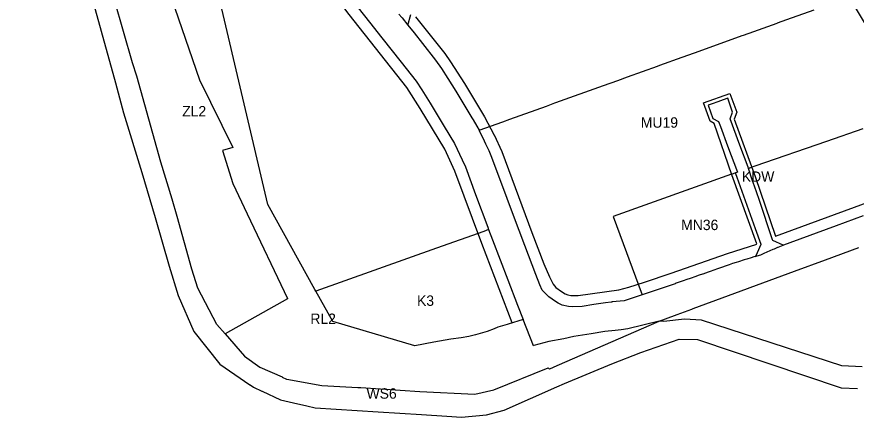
# Model space of a CAD drawing. Extents: x 7428080 to 7432143, y 5545880 to 5549217.
# Drawn here: x 7430737.9 to 7431185, y 5546637.9 to 5546851.1 of the extents above; entities that cross this region are included whole.
import ezdxf

# ---------------------------------------------------------------- set-up
doc = ezdxf.new("R2010")
doc.units = 0
for name, color, linetype in [('CZ_L_linie rozgraniczające tereny o różnym przeznaczeniu oraz różnych warunkach ich zabudowy i zagospodarowania', 7, 'Continuous'), ('CZ_L_maksymalne nieprzekraczalne linie zabudowy', 7, 'Continuous'), ('CZ_L_opisy_linie rozgraniczające tereny o różnym przeznaczeniu oraz różnych warunkach ich zabudowy i zagospodarowania', 7, 'Continuous')]:
    doc.layers.add(name, color=color, linetype=linetype)

msp = doc.modelspace()

# ---------------------------------------------------------------- linework, layer by layer
at = {"layer": 'CZ_L_linie rozgraniczające tereny o różnym przeznaczeniu oraz różnych warunkach ich zabudowy i zagospodarowania'}
for p, q in [((7430772.09, 5546882.16), (7430782.77, 5546843.47)), ((7430816.73, 5546871.65), (7430835.13, 5546817.59)), ((7430871.63, 5546751.13), (7430842.37, 5546875.38)), ((7430799.48, 5546826.52), (7430789.89, 5546859.94)), ((7430919.75, 5546855.93), (7430925.7, 5546848.35)), ((7431148.11, 5546849.64), (7431162.61, 5546854.85)), ((7430941.47, 5546852.61), (7430942.98, 5546850.71)), ((7430942.98, 5546850.71), (7430943.1, 5546850.55)), ((7430943.1, 5546850.55), (7430946.25, 5546846.58)), ((7430946.25, 5546846.58), (7430947.77, 5546852.28)), ((7431143.09, 5546847.84), (7431148.11, 5546849.64)), ((7430925.7, 5546848.35), (7430932.34, 5546839.98)), ((7430946.25, 5546846.58), (7430949.49, 5546842.5)), ((7431130.47, 5546843.3), (7431142.95, 5546847.79)), ((7431142.95, 5546847.79), (7431143.09, 5546847.84)), ((7430782.77, 5546843.47), (7430790.38, 5546816)), ((7430949.49, 5546842.5), (7430953.96, 5546836.87)), ((7431101.34, 5546832.83), (7431124.29, 5546841.08)), ((7431124.29, 5546841.08), (7431124.96, 5546841.32)), ((7431124.96, 5546841.32), (7431130.47, 5546843.3)), ((7430932.34, 5546839.98), (7430942.62, 5546827.04)), ((7430953.96, 5546836.87), (7430960.97, 5546828.08)), ((7431092.28, 5546829.58), (7431098.94, 5546831.97)), ((7431098.94, 5546831.97), (7431101.34, 5546832.83)), ((7430942.62, 5546827.04), (7430950.62, 5546816.8)), ((7430960.97, 5546828.08), (7430964.09, 5546823.59)), ((7431080.47, 5546825.33), (7431092.28, 5546829.58)), ((7430801.85, 5546819.49), (7430799.48, 5546826.52)), ((7430964.09, 5546823.59), (7430967.54, 5546818.25)), ((7431063.25, 5546819.15), (7431079.15, 5546824.86)), ((7431079.15, 5546824.86), (7431080.47, 5546825.33)), ((7430814.59, 5546773.7), (7430801.85, 5546819.49)), ((7430967.54, 5546818.25), (7430971.78, 5546811.47)), ((7431057.96, 5546817.25), (7431063.25, 5546819.15)), ((7430790.38, 5546816), (7430794.65, 5546799.9)), ((7430835.13, 5546817.59), (7430852.91, 5546781.48)), ((7430950.62, 5546816.8), (7430953.57, 5546812.23)), ((7431025, 5546805.4), (7431050.35, 5546814.51)), ((7431050.35, 5546814.51), (7431057.96, 5546817.25)), ((7430953.57, 5546812.23), (7430958.13, 5546805.06)), ((7430971.78, 5546811.47), (7430975.49, 5546805.32)), ((7430958.13, 5546805.06), (7430965.59, 5546792.7)), ((7430975.49, 5546805.32), (7430980.3, 5546797.35)), ((7431019.98, 5546803.6), (7431024.52, 5546805.23)), ((7431024.52, 5546805.23), (7431025, 5546805.4)), ((7431108.36, 5546804.79), (7431106.19, 5546804.01)), ((7431111.3, 5546805.84), (7431108.36, 5546804.79)), ((7431114.17, 5546806.87), (7431111.3, 5546805.84)), ((7431116.64, 5546807.75), (7431114.17, 5546806.87)), ((7431119.21, 5546800.25), (7431116.64, 5546807.75)), ((7431000.48, 5546796.59), (7431019.98, 5546803.6)), ((7431106.19, 5546804.01), (7431108.63, 5546796.89)), ((7431117.91, 5546796.73), (7431119.21, 5546800.25)), ((7430794.65, 5546799.9), (7430804.53, 5546768.24)), ((7430980.3, 5546797.35), (7430980.94, 5546796.3)), ((7430980.94, 5546796.3), (7430982.96, 5546792.95)), ((7430996.75, 5546795.25), (7431000.48, 5546796.59)), ((7431108.63, 5546796.89), (7431111.74, 5546795.33)), ((7431123.08, 5546782.72), (7431117.91, 5546796.73)), ((7430965.59, 5546792.7), (7430971.02, 5546783.71)), ((7430982.96, 5546792.95), (7430984.24, 5546790.75)), ((7430984.24, 5546790.75), (7430996.75, 5546795.25)), ((7431111.74, 5546795.33), (7431112.71, 5546792.62)), ((7431112.71, 5546792.62), (7431116.51, 5546782.44)), ((7431188.57, 5546791.51), (7431169.17, 5546784.73)), ((7430984.42, 5546790.45), (7430984.24, 5546790.75)), ((7430987.03, 5546784.91), (7430984.42, 5546790.45)), ((7430971.02, 5546783.71), (7430975.11, 5546775.01)), ((7430987.8, 5546783.27), (7430987.03, 5546784.91)), ((7430989.46, 5546779.75), (7430987.8, 5546783.27)), ((7431116.51, 5546782.44), (7431121.82, 5546768.34)), ((7431127.39, 5546771.04), (7431123.08, 5546782.72)), ((7431169.17, 5546784.73), (7431131.02, 5546771.55)), ((7430852.91, 5546781.48), (7430847.46, 5546779.98)), ((7430847.46, 5546779.98), (7430852.88, 5546762.35)), ((7430990.6, 5546777.16), (7430989.46, 5546779.75)), ((7430820.58, 5546753.96), (7430814.59, 5546773.7)), ((7430975.11, 5546775.01), (7430976.82, 5546771.2)), ((7430995.73, 5546763.44), (7430990.6, 5546777.16)), ((7430976.82, 5546771.2), (7430982.29, 5546756.46)), ((7431127.62, 5546770.36), (7431127.39, 5546771.04)), ((7431129.85, 5546763.84), (7431127.62, 5546770.36)), ((7431127.64, 5546770.36), (7431127.62, 5546770.36)), ((7431128.09, 5546770.52), (7431127.64, 5546770.36)), ((7431128.1, 5546770.52), (7431128.09, 5546770.52)), ((7431128.09, 5546770.52), (7431128.09, 5546770.52)), ((7431129.63, 5546771.05), (7431128.1, 5546770.52)), ((7431130.45, 5546771.34), (7431129.63, 5546771.05)), ((7431131.02, 5546771.55), (7431130.45, 5546771.34)), ((7430804.53, 5546768.24), (7430811.51, 5546744.22)), ((7431118.57, 5546767.23), (7431055.53, 5546744.83)), ((7431120.64, 5546767.94), (7431118.57, 5546767.22)), ((7431118.57, 5546767.22), (7431118.57, 5546767.23)), ((7431120.83, 5546768), (7431120.64, 5546767.94)), ((7431120.64, 5546767.94), (7431120.72, 5546767.69)), ((7431120.72, 5546767.69), (7431121.4, 5546765.66)), ((7431120.84, 5546768), (7431120.83, 5546768)), ((7431121.82, 5546768.34), (7431120.84, 5546768)), ((7431121.4, 5546765.66), (7431122.25, 5546763.3)), ((7430852.88, 5546762.35), (7430860.57, 5546746.21)), ((7431002.43, 5546745.33), (7430995.73, 5546763.44)), ((7431122.25, 5546763.3), (7431125.86, 5546753.26)), ((7431130.87, 5546760.85), (7431129.85, 5546763.84)), ((7431133.25, 5546753.82), (7431130.87, 5546760.85)), ((7430982.29, 5546756.46), (7430988.75, 5546739.07)), ((7430823.22, 5546744.69), (7430820.58, 5546753.96)), ((7430896.7, 5546705.86), (7430871.63, 5546751.13)), ((7431125.86, 5546753.26), (7431131.23, 5546738.31)), ((7431140.52, 5546732.35), (7431133.25, 5546753.82)), ((7430811.51, 5546744.22), (7430819.04, 5546718.3)), ((7430831.19, 5546716.65), (7430823.22, 5546744.69)), ((7430860.57, 5546746.21), (7430882.08, 5546701.06)), ((7431008.44, 5546729.25), (7431002.43, 5546745.33)), ((7431055.53, 5546744.83), (7431070.93, 5546703.01)), ((7431188.68, 5546745.1), (7431174.41, 5546739.84)), ((7430989.18, 5546737.92), (7430986.58, 5546736.8)), ((7430988.75, 5546739.07), (7430989.18, 5546737.92)), ((7430989.18, 5546737.92), (7430991.22, 5546732.43)), ((7431131.23, 5546738.31), (7431134.2, 5546730.07)), ((7431174.41, 5546739.84), (7431149.72, 5546730.73)), ((7430986.58, 5546736.8), (7430961.52, 5546727.84)), ((7430991.22, 5546732.43), (7430999.45, 5546710.98)), ((7431014.4, 5546713.93), (7431008.44, 5546729.25)), ((7431134.29, 5546729.81), (7431132.2, 5546725.39)), ((7431134.2, 5546730.07), (7431134.29, 5546729.81)), ((7431140.64, 5546732.02), (7431140.52, 5546732.35)), ((7431146.17, 5546729.42), (7431140.64, 5546732.02)), ((7431143.41, 5546728.4), (7431146.17, 5546729.42)), ((7431146.24, 5546729.45), (7431146.17, 5546729.42)), ((7431149.72, 5546730.73), (7431146.24, 5546729.45)), ((7430961.52, 5546727.84), (7430897.15, 5546705.04)), ((7431132.2, 5546725.39), (7431131.33, 5546723.52)), ((7431131.76, 5546723.66), (7431133.49, 5546724.21)), ((7431133.49, 5546724.21), (7431134.21, 5546724.44)), ((7431134.2, 5546724.44), (7431136.01, 5546725.22)), ((7431134.21, 5546724.44), (7431134.2, 5546724.44)), ((7431136.01, 5546725.22), (7431140.82, 5546727.29)), ((7431140.82, 5546727.29), (7431141.54, 5546727.6)), ((7431141.54, 5546727.6), (7431143.32, 5546728.37)), ((7431143.32, 5546728.37), (7431143.38, 5546728.47)), ((7431143.38, 5546728.47), (7431143.41, 5546728.4)), ((7431168.64, 5546721.72), (7431186.42, 5546728.28)), ((7431119.17, 5546719.67), (7431117.4, 5546719.05)), ((7431121.03, 5546720.26), (7431119.17, 5546719.67)), ((7431122.29, 5546720.66), (7431121.03, 5546720.26)), ((7431125.33, 5546721.62), (7431122.29, 5546720.66)), ((7431126.78, 5546722.08), (7431125.33, 5546721.62)), ((7431129, 5546722.78), (7431126.78, 5546722.08)), ((7431130.46, 5546723.25), (7431129, 5546722.78)), ((7431131.33, 5546723.52), (7431130.46, 5546723.25)), ((7431131.33, 5546723.52), (7431131.43, 5546723.55)), ((7431131.43, 5546723.55), (7431131.76, 5546723.66)), ((7431152.23, 5546715.67), (7431168.64, 5546721.72)), ((7430819.04, 5546718.3), (7430823.84, 5546702.63)), ((7430834.35, 5546706.63), (7430831.19, 5546716.65)), ((7431106.18, 5546715.14), (7431103.26, 5546714.11)), ((7431107.24, 5546715.51), (7431106.18, 5546715.14)), ((7431111.19, 5546716.89), (7431107.24, 5546715.51)), ((7431112.65, 5546717.4), (7431111.19, 5546716.89)), ((7431116.33, 5546718.68), (7431112.65, 5546717.4)), ((7431117.4, 5546719.05), (7431116.33, 5546718.68)), ((7431138.68, 5546710.67), (7431152.23, 5546715.67)), ((7430999.45, 5546710.98), (7431004.66, 5546697.59)), ((7431016.54, 5546708.44), (7431014.4, 5546713.93)), ((7431093.45, 5546710.69), (7431088.67, 5546709.02)), ((7431094.22, 5546710.96), (7431093.45, 5546710.69)), ((7431097.16, 5546711.99), (7431094.22, 5546710.96)), ((7431099.01, 5546712.63), (7431097.16, 5546711.99)), ((7431101.36, 5546713.45), (7431099.01, 5546712.63)), ((7431103.06, 5546714.04), (7431101.36, 5546713.45)), ((7431103.26, 5546714.11), (7431103.06, 5546714.04)), ((7431117.06, 5546702.7), (7431138.68, 5546710.67)), ((7430844.47, 5546687.26), (7430834.35, 5546706.63)), ((7431017.69, 5546705.46), (7431016.54, 5546708.44)), ((7431088.64, 5546708.99), (7431070.93, 5546703.01)), ((7431088.67, 5546709.02), (7431088.64, 5546708.99)), ((7430823.84, 5546702.63), (7430832.19, 5546683.49)), ((7430897.15, 5546705.04), (7430896.7, 5546705.86)), ((7430906.15, 5546688.8), (7430897.15, 5546705.04)), ((7431021.33, 5546701.99), (7431017.69, 5546705.46)), ((7431024.9, 5546699.56), (7431021.33, 5546701.99)), ((7431069.44, 5546702.51), (7431061.35, 5546699.78)), ((7431070.93, 5546703.01), (7431069.44, 5546702.51)), ((7431098.21, 5546695.75), (7431117.06, 5546702.7)), ((7430882.14, 5546700.92), (7430848.83, 5546682.2)), ((7430882.08, 5546701.06), (7430882.14, 5546700.93)), ((7430882.14, 5546700.93), (7430882.14, 5546700.92)), ((7431004.66, 5546697.59), (7431004.67, 5546697.6)), ((7431004.67, 5546697.6), (7431007.63, 5546689.94)), ((7431026.23, 5546698.66), (7431024.9, 5546699.56)), ((7431028.35, 5546697.5), (7431026.23, 5546698.66)), ((7431031.74, 5546696.88), (7431028.35, 5546697.5)), ((7431045.21, 5546697.87), (7431039.07, 5546696.76)), ((7431051.48, 5546698.77), (7431045.21, 5546697.87)), ((7431054.56, 5546699.2), (7431051.48, 5546698.77)), ((7431054.78, 5546699.23), (7431054.56, 5546699.2)), ((7431055.03, 5546699.24), (7431054.78, 5546699.23)), ((7431061.35, 5546699.78), (7431055.03, 5546699.24)), ((7431033.82, 5546696.62), (7431031.74, 5546696.88)), ((7431039.07, 5546696.76), (7431033.82, 5546696.62)), ((7431089.62, 5546692.58), (7431097.47, 5546695.48)), ((7431097.47, 5546695.48), (7431098.21, 5546695.75)), ((7430949.92, 5546675.88), (7430906.15, 5546688.8)), ((7431007.63, 5546689.94), (7430999.6, 5546687.51)), ((7431013.05, 5546675.95), (7431007.63, 5546689.94)), ((7431025.81, 5546665.34), (7431080.08, 5546689.06)), ((7431080.08, 5546689.06), (7431063.44, 5546684.99)), ((7431080.08, 5546689.06), (7431083.42, 5546690.3)), ((7431082.55, 5546688.78), (7431080.08, 5546689.06)), ((7431093.51, 5546690.01), (7431082.55, 5546688.78)), ((7431083.42, 5546690.3), (7431089.62, 5546692.58)), ((7431102.56, 5546689.5), (7431093.51, 5546690.01)), ((7431177.42, 5546665.27), (7431102.56, 5546689.5)), ((7430848.83, 5546682.2), (7430844.47, 5546687.26)), ((7430992.14, 5546684.99), (7430988.52, 5546683.6)), ((7430994.17, 5546685.77), (7430992.14, 5546684.99)), ((7430999.04, 5546687.34), (7430994.17, 5546685.77)), ((7430999.59, 5546687.5), (7430999.04, 5546687.34)), ((7430999.6, 5546687.51), (7430999.59, 5546687.5)), ((7431056.71, 5546684.13), (7431051.05, 5546683.61)), ((7431059.76, 5546684.43), (7431056.71, 5546684.13)), ((7431063.44, 5546684.99), (7431059.76, 5546684.43)), ((7430832.19, 5546683.49), (7430846.02, 5546666.14)), ((7430848.83, 5546682.2), (7430859.16, 5546670.33)), ((7430969.03, 5546679.41), (7430959.97, 5546677.82)), ((7430974.66, 5546680.2), (7430969.03, 5546679.41)), ((7430978.76, 5546680.94), (7430974.66, 5546680.2)), ((7430982.28, 5546681.81), (7430978.76, 5546680.94)), ((7430988.52, 5546683.6), (7430982.28, 5546681.81)), ((7431029.29, 5546679.59), (7431021.34, 5546678.21)), ((7431034.66, 5546680.86), (7431029.29, 5546679.59)), ((7431043.83, 5546682.36), (7431034.66, 5546680.86)), ((7431051.05, 5546683.61), (7431043.83, 5546682.36)), ((7431070.21, 5546672.43), (7431090.68, 5546679.42)), ((7431090.68, 5546679.42), (7431100.57, 5546679.2)), ((7430959.97, 5546677.82), (7430949.92, 5546675.88)), ((7431013.34, 5546676.03), (7431013.05, 5546675.95)), ((7431021.34, 5546678.21), (7431013.34, 5546676.03)), ((7431100.57, 5546679.2), (7431176.99, 5546653.49)), ((7431054.77, 5546666.23), (7431070.21, 5546672.43)), ((7430846.02, 5546666.14), (7430862.09, 5546655.19)), ((7430859.16, 5546670.33), (7430867.43, 5546664.62)), ((7431029.7, 5546655.82), (7431054.77, 5546666.23)), ((7430867.43, 5546664.62), (7430879.18, 5546659.32)), ((7430992.07, 5546652.38), (7431020.92, 5546664.18)), ((7431020.92, 5546664.18), (7431021.59, 5546663.5)), ((7431021.59, 5546663.5), (7431021.75, 5546663.57)), ((7431021.75, 5546663.57), (7431025.81, 5546665.34)), ((7431188.16, 5546664.65), (7431177.42, 5546665.27)), ((7430879.18, 5546659.32), (7430879.25, 5546659.29)), ((7430879.25, 5546659.29), (7430881.62, 5546658.22)), ((7430881.62, 5546658.22), (7430881.65, 5546658.23)), ((7430881.65, 5546658.23), (7430881.66, 5546658.2)), ((7430881.66, 5546658.2), (7430900.33, 5546654.72)), ((7430862.09, 5546655.19), (7430862.13, 5546655.2)), ((7430862.13, 5546655.2), (7430863.99, 5546653.97)), ((7430863.99, 5546653.97), (7430868.38, 5546651.84)), ((7430900.33, 5546654.72), (7430919.56, 5546653.65)), ((7430919.56, 5546653.65), (7430919.81, 5546653.71)), ((7430919.81, 5546653.71), (7430921.06, 5546653.65)), ((7430921.06, 5546653.65), (7430952.64, 5546651.61)), ((7430997.51, 5546641.56), (7431025.51, 5546654.07)), ((7431025.51, 5546654.07), (7431029.7, 5546655.82)), ((7431176.99, 5546653.49), (7431185.7, 5546653.13)), ((7430868.38, 5546651.84), (7430868.53, 5546651.76)), ((7430868.53, 5546651.76), (7430878.37, 5546647.06)), ((7430952.64, 5546651.61), (7430981.82, 5546650.19)), ((7430981.82, 5546650.19), (7430992.07, 5546652.38)), ((7430878.37, 5546647.06), (7430885.35, 5546645.5)), ((7430885.35, 5546645.5), (7430892.39, 5546643.92)), ((7430892.39, 5546643.92), (7430896.86, 5546642.92)), ((7430896.86, 5546642.92), (7430930.36, 5546640.82)), ((7430930.36, 5546640.82), (7430953.48, 5546639.36)), ((7430953.48, 5546639.36), (7430966.94, 5546638.43)), ((7430974.73, 5546637.88), (7430988.1, 5546639.23)), ((7430988.1, 5546639.23), (7430997.51, 5546641.56)), ((7430966.94, 5546638.43), (7430974.73, 5546637.88))]:
    msp.add_line(p, q, dxfattribs=at)
at = {"layer": 'CZ_L_maksymalne nieprzekraczalne linie zabudowy'}
for points in [[(7431001.77, 5546688.14), (7430985.61, 5546730.31), (7430971.26, 5546768.92), (7430965.85, 5546780.6), (7430952.8, 5546802.25), (7430945.6, 5546813.48), (7430915, 5546852.27), (7430908.72, 5546860.69), (7430907, 5546862.78), (7430903.21, 5546869.02), (7430898.44, 5546877.88), (7430897.33, 5546880.63), (7430894.86, 5546887.15), (7430882.68, 5546923.15), (7430879.42, 5546929.87), (7430874.82, 5546937.03), (7430866.55, 5546947.03), (7430812.62, 5547004.67), (7430797.81, 5547020.91), (7430765.98, 5547058.41), (7430743.74, 5547085.12), (7430692.31, 5547149.26)], [(7431141.98, 5546734.3), (7431201.48, 5546756.15), (7431213.71, 5546759.85), (7431227.5, 5546763.18), (7431238.99, 5546764.95), (7431252.37, 5546765.87), (7431257.66, 5546765.8), (7431269.33, 5546763.72), (7431268.74, 5546769.43), (7431267.3, 5546771.6), (7431231.51, 5546796.51), (7431229.84, 5546798.06), (7431212.56, 5546817.77), (7431193.31, 5546842.22), (7431189.98, 5546847.26), (7431185.11, 5546855.13), (7431184.36, 5546856.6)], [(7430950.34, 5546851.11), (7430965.82, 5546831.62), (7430968.98, 5546827.06), (7430976.3, 5546815.55), (7430987.04, 5546797.79), (7430992.13, 5546788.08)], [(7431132.16, 5546730.2), (7431118.79, 5546767), (7431109.29, 5546794.34), (7431107.16, 5546795.53), (7431103.65, 5546805.23), (7431117.74, 5546810.27), (7431121.41, 5546800.27), (7431119.93, 5546796.64), (7431131.2, 5546766.09), (7431141.97, 5546734.31)], [(7430992.11, 5546788.2), (7430996.18, 5546779.37), (7431012.23, 5546736.29), (7431018.67, 5546719.62), (7431021.59, 5546712.57), (7431023.55, 5546708.67), (7431024.94, 5546706.96), (7431027.95, 5546704.76), (7431029.95, 5546703.5), (7431031.42, 5546703.05), (7431033.09, 5546702.77), (7431036.85, 5546702.74), (7431058.65, 5546705.79), (7431063.95, 5546707.2), (7431072.23, 5546709.82), (7431086.39, 5546714.58), (7431116.53, 5546725.1), (7431132.07, 5546730.05)]]:
    msp.add_lwpolyline(points, dxfattribs=at)

# ---------------------------------------------------------------- texts
at = {"layer": 'CZ_L_opisy_linie rozgraniczające tereny o różnym przeznaczeniu oraz różnych warunkach ich zabudowy i zagospodarowania'}
for s, p in [('ZL2', (7430825.98, 5546798.07)), ('MU19', (7431070.31, 5546792.06)), ('KDW', (7431124.11, 5546763.24)), ('MN36', (7431091.78, 5546737.53)), ('K3', (7430951.08, 5546697.18)), ('RL2', (7430894.26, 5546687.54)), ('WS6', (7430924.18, 5546647.74))]:
    msp.add_text(s, height=5.549, dxfattribs=at).set_placement(p)

doc.saveas('drawing.dxf')
